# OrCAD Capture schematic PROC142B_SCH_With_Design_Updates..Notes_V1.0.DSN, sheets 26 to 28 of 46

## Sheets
26 25. CPSW RGMII_2 ETHERNET PHY: size C; title: CPSW3G RGMII_2 ETHERNET PHY
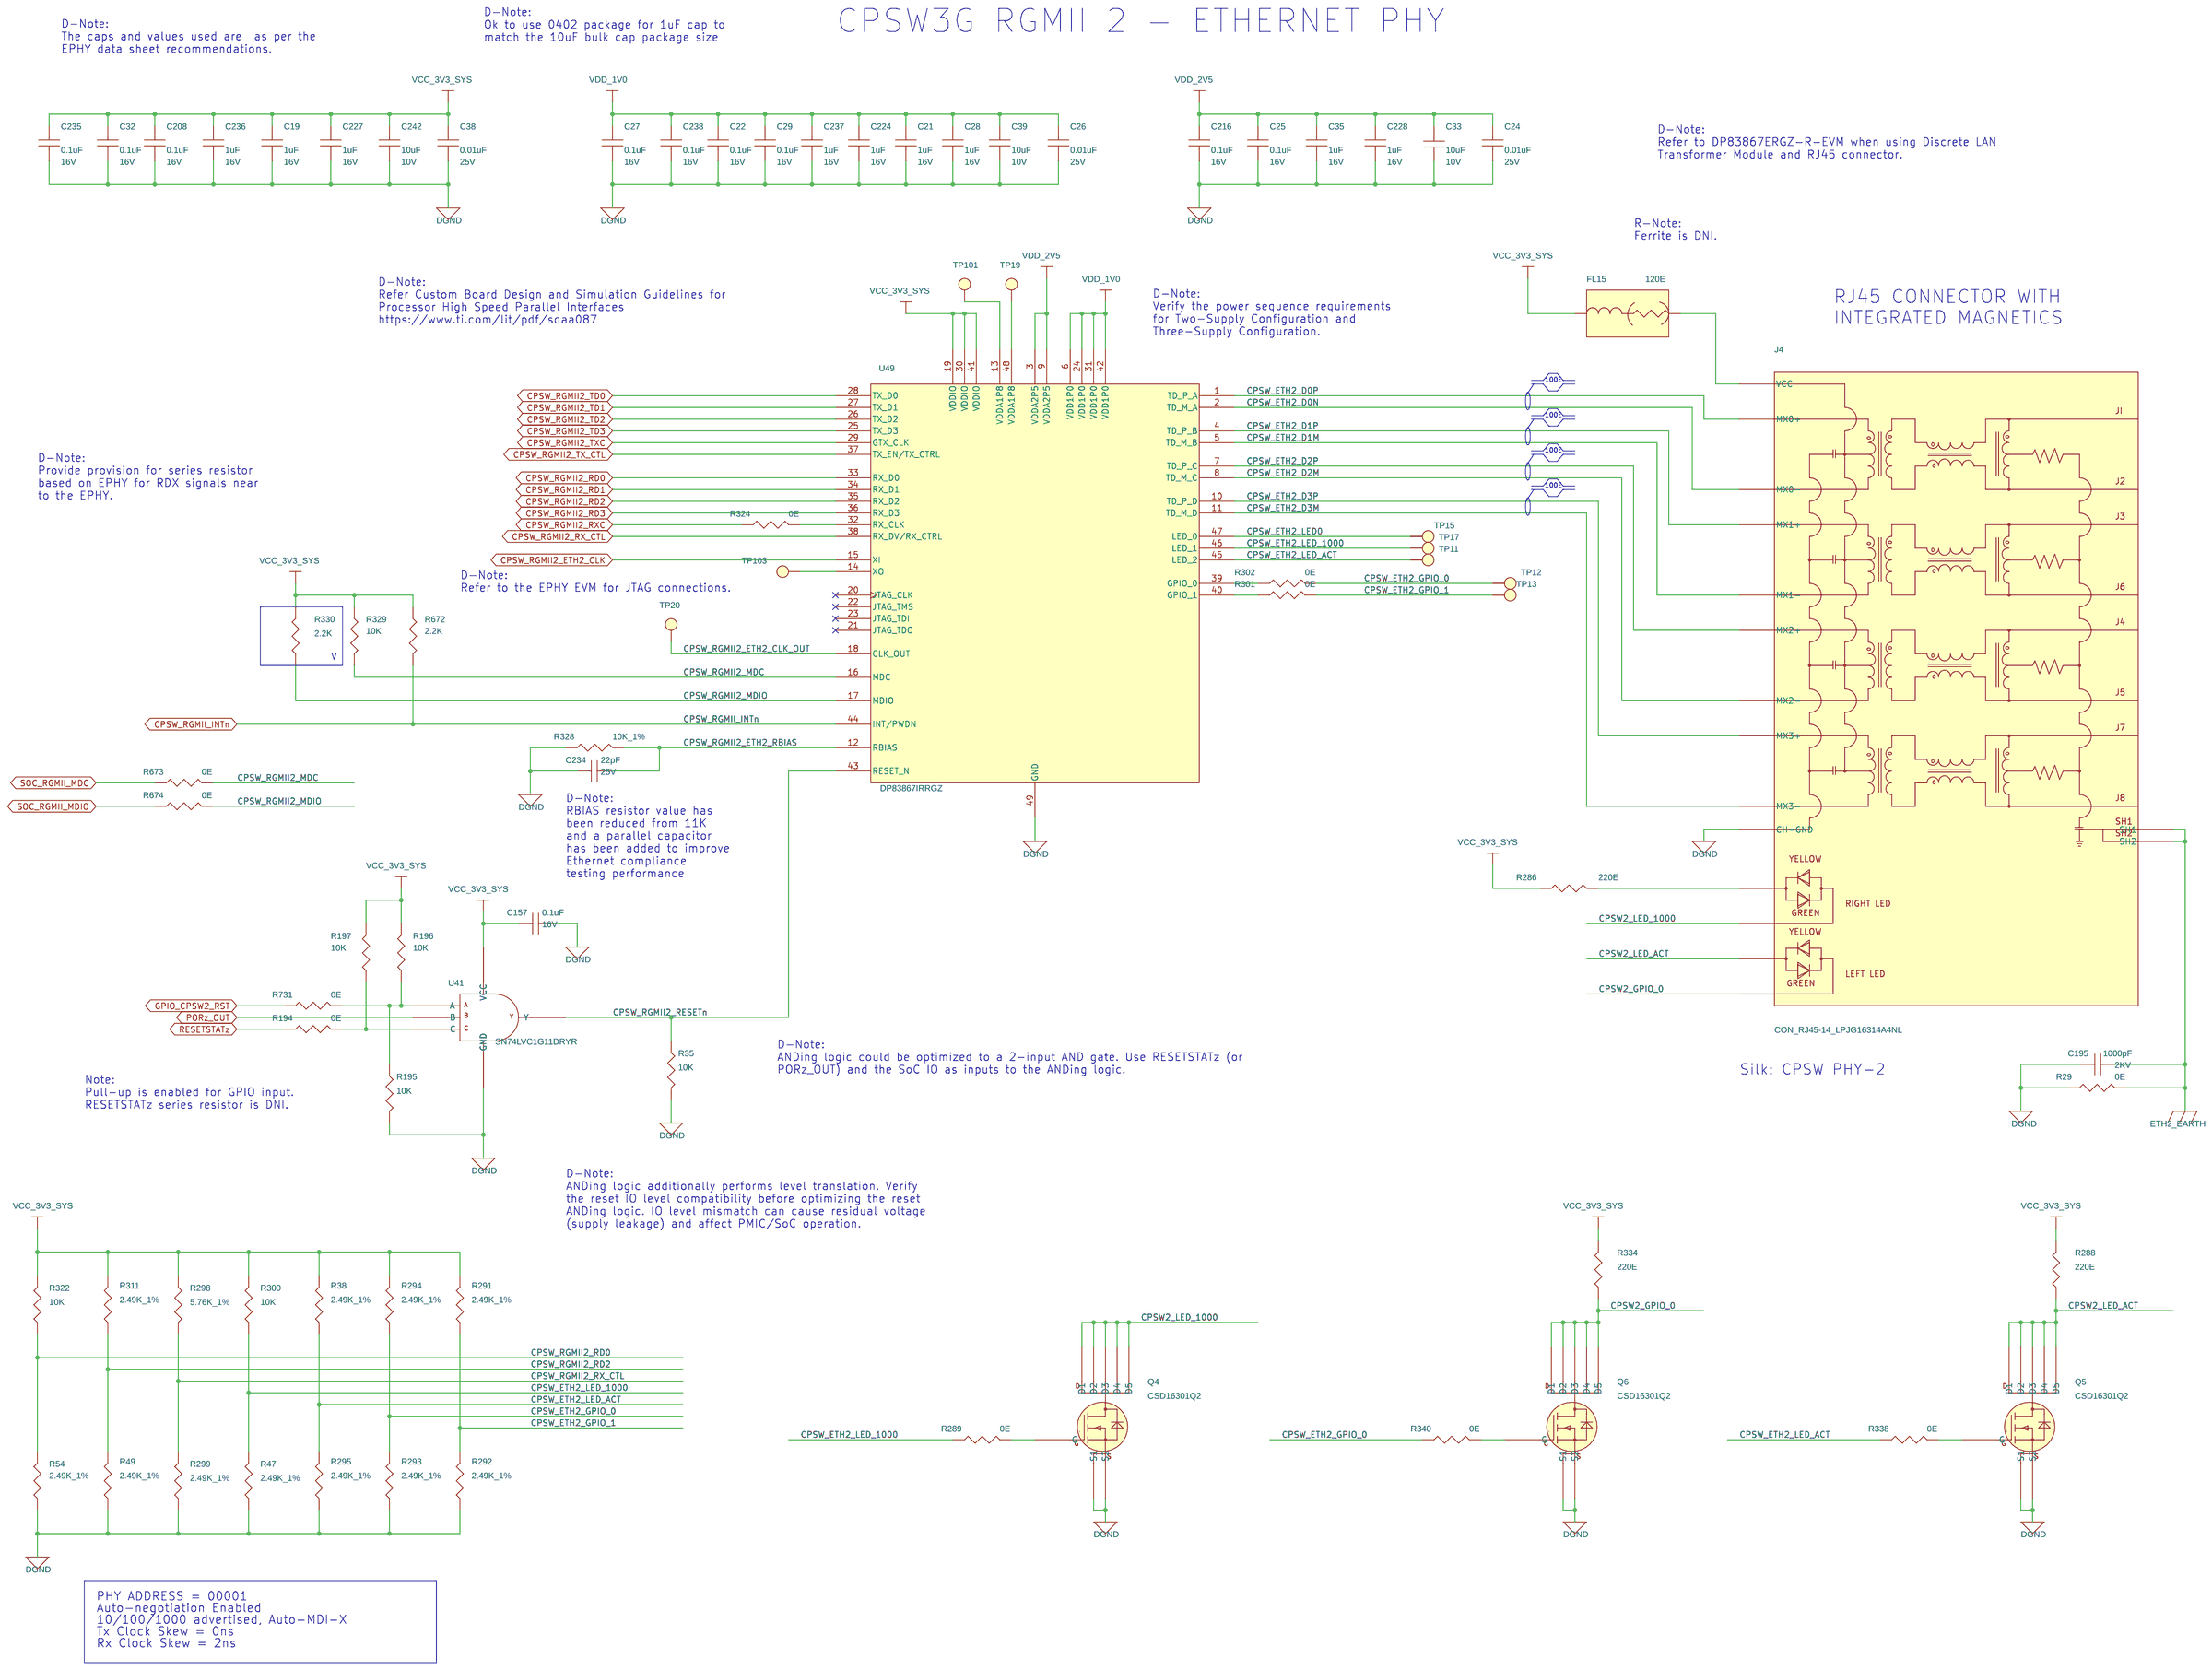
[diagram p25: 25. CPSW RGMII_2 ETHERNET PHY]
27 26. PHY CLK & LED DRIVER: size C; title: SOC MAC INTRFACE, SOC AND ETHERNET PHYs CLOCK BUFFER, LED DRIVER
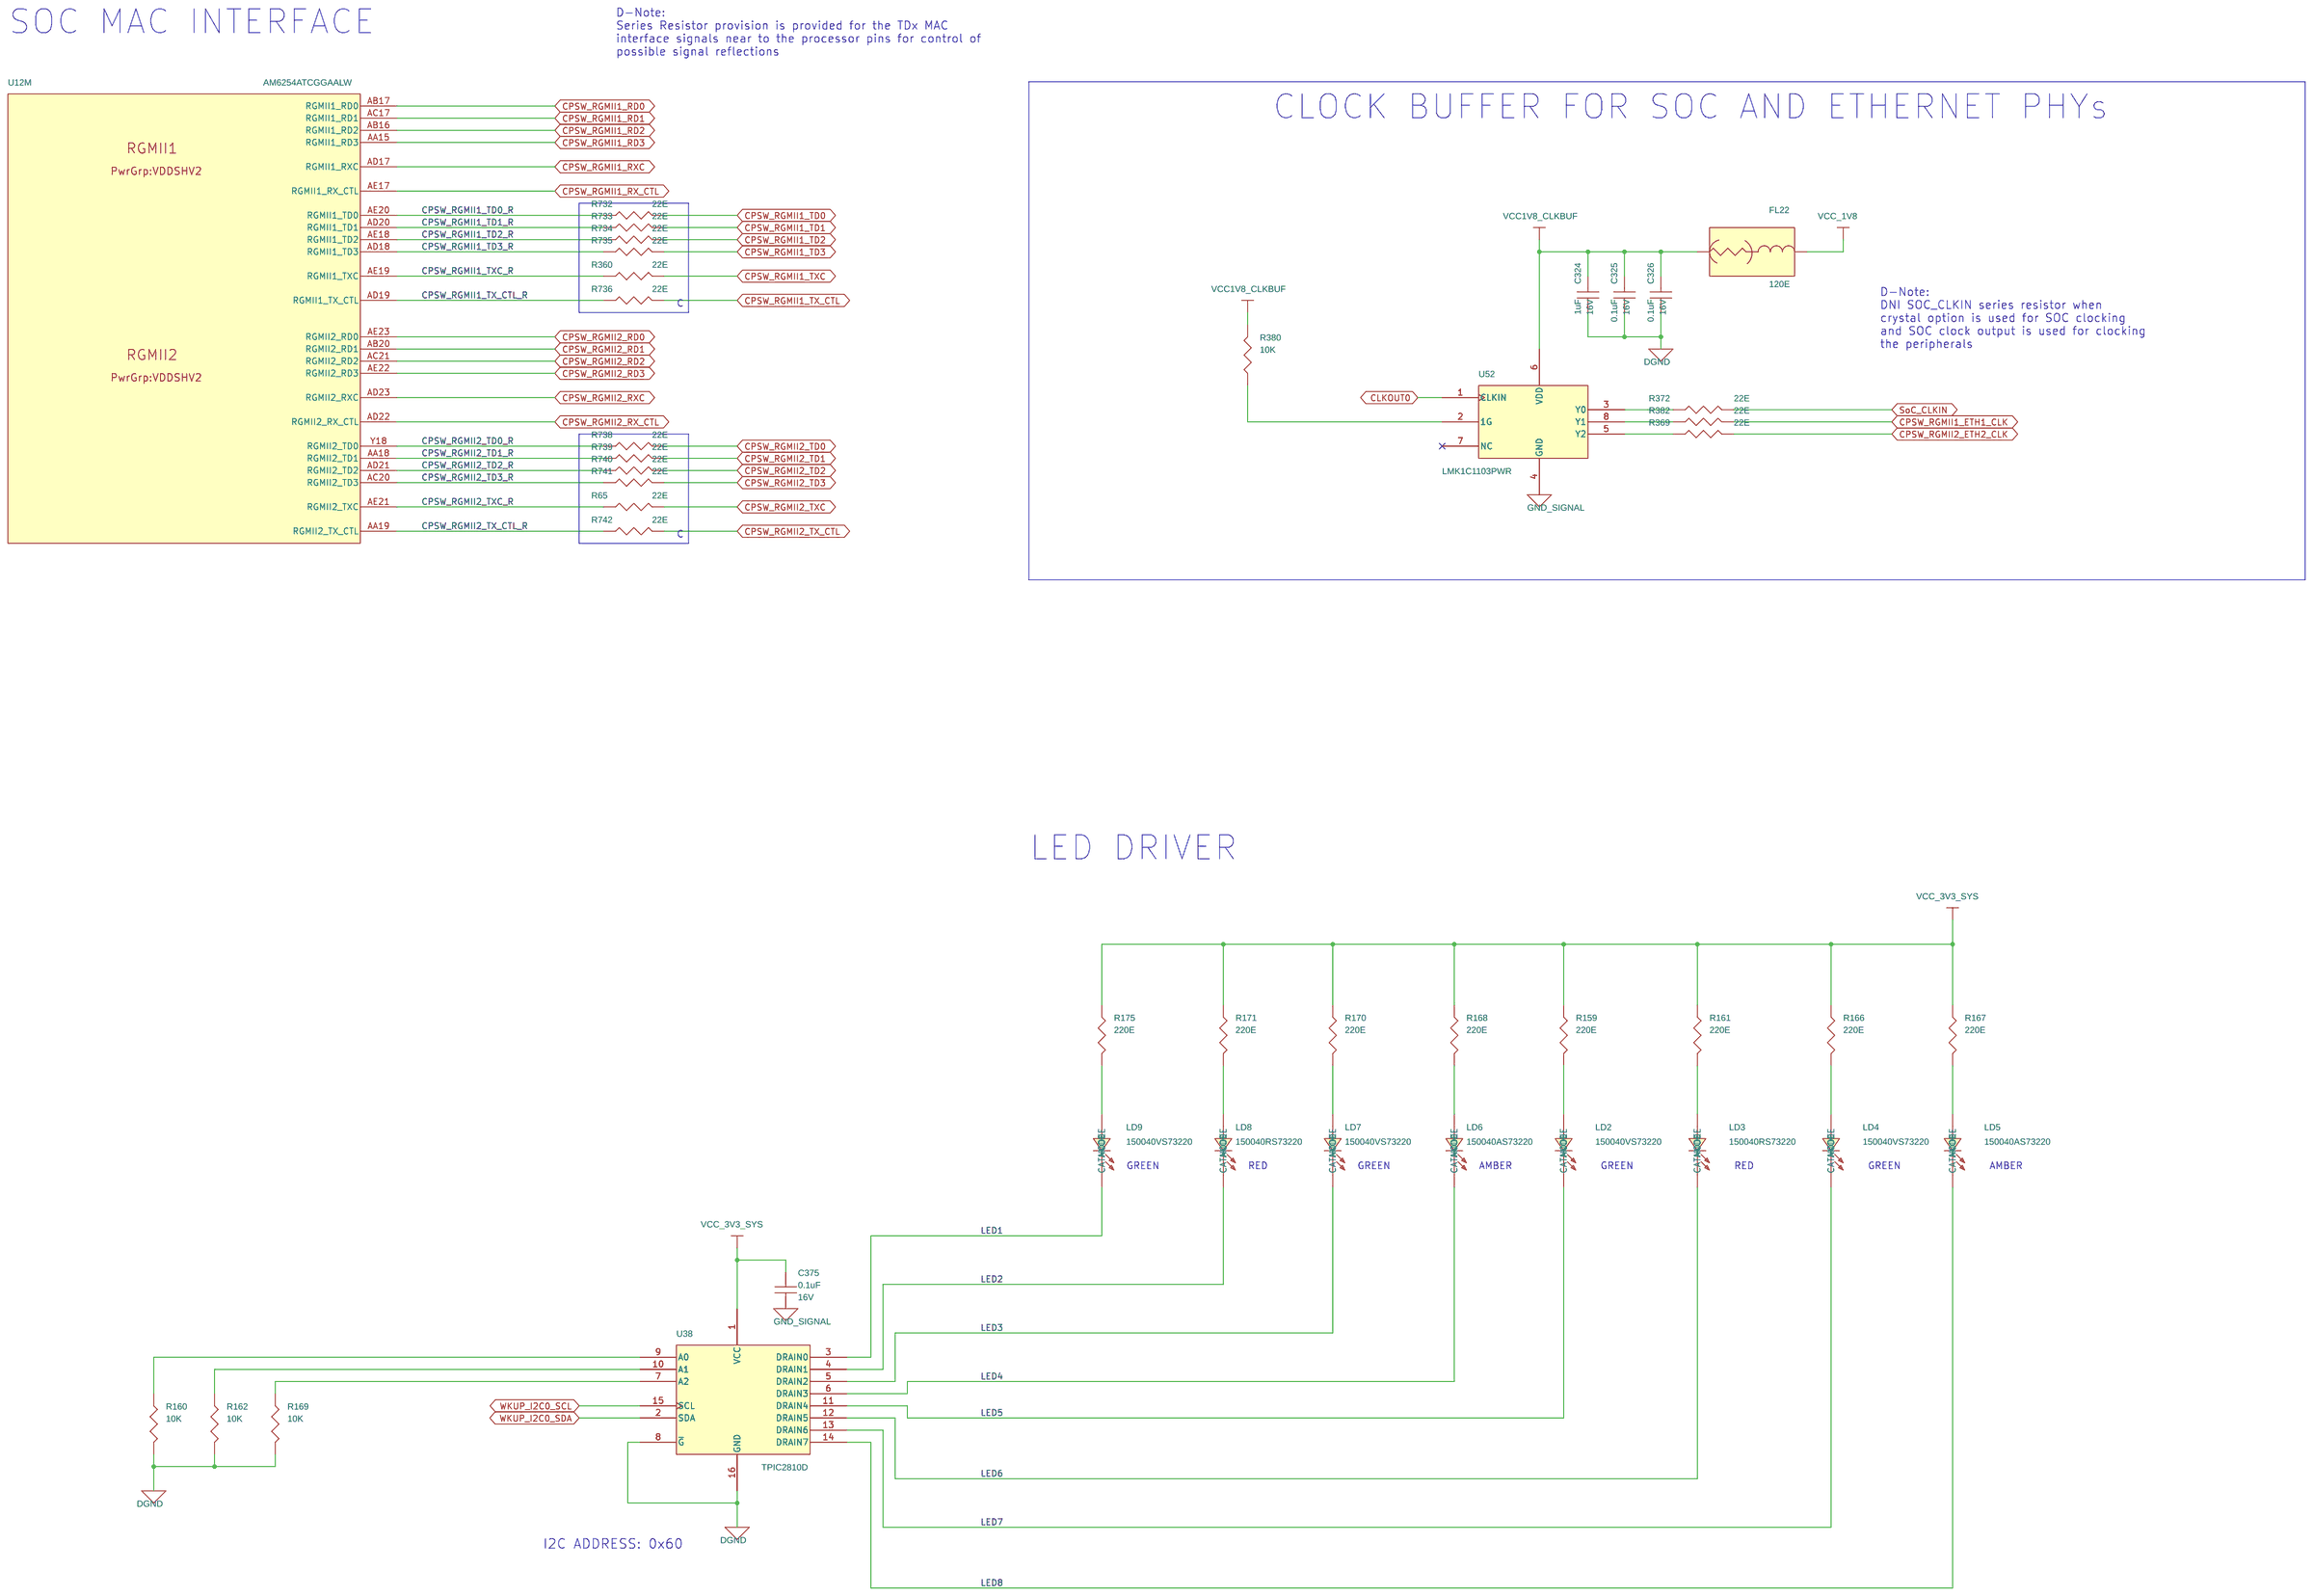
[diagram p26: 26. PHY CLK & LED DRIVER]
28 27. TEST AUTOMATION: size C; title: TEST AUTOMATION
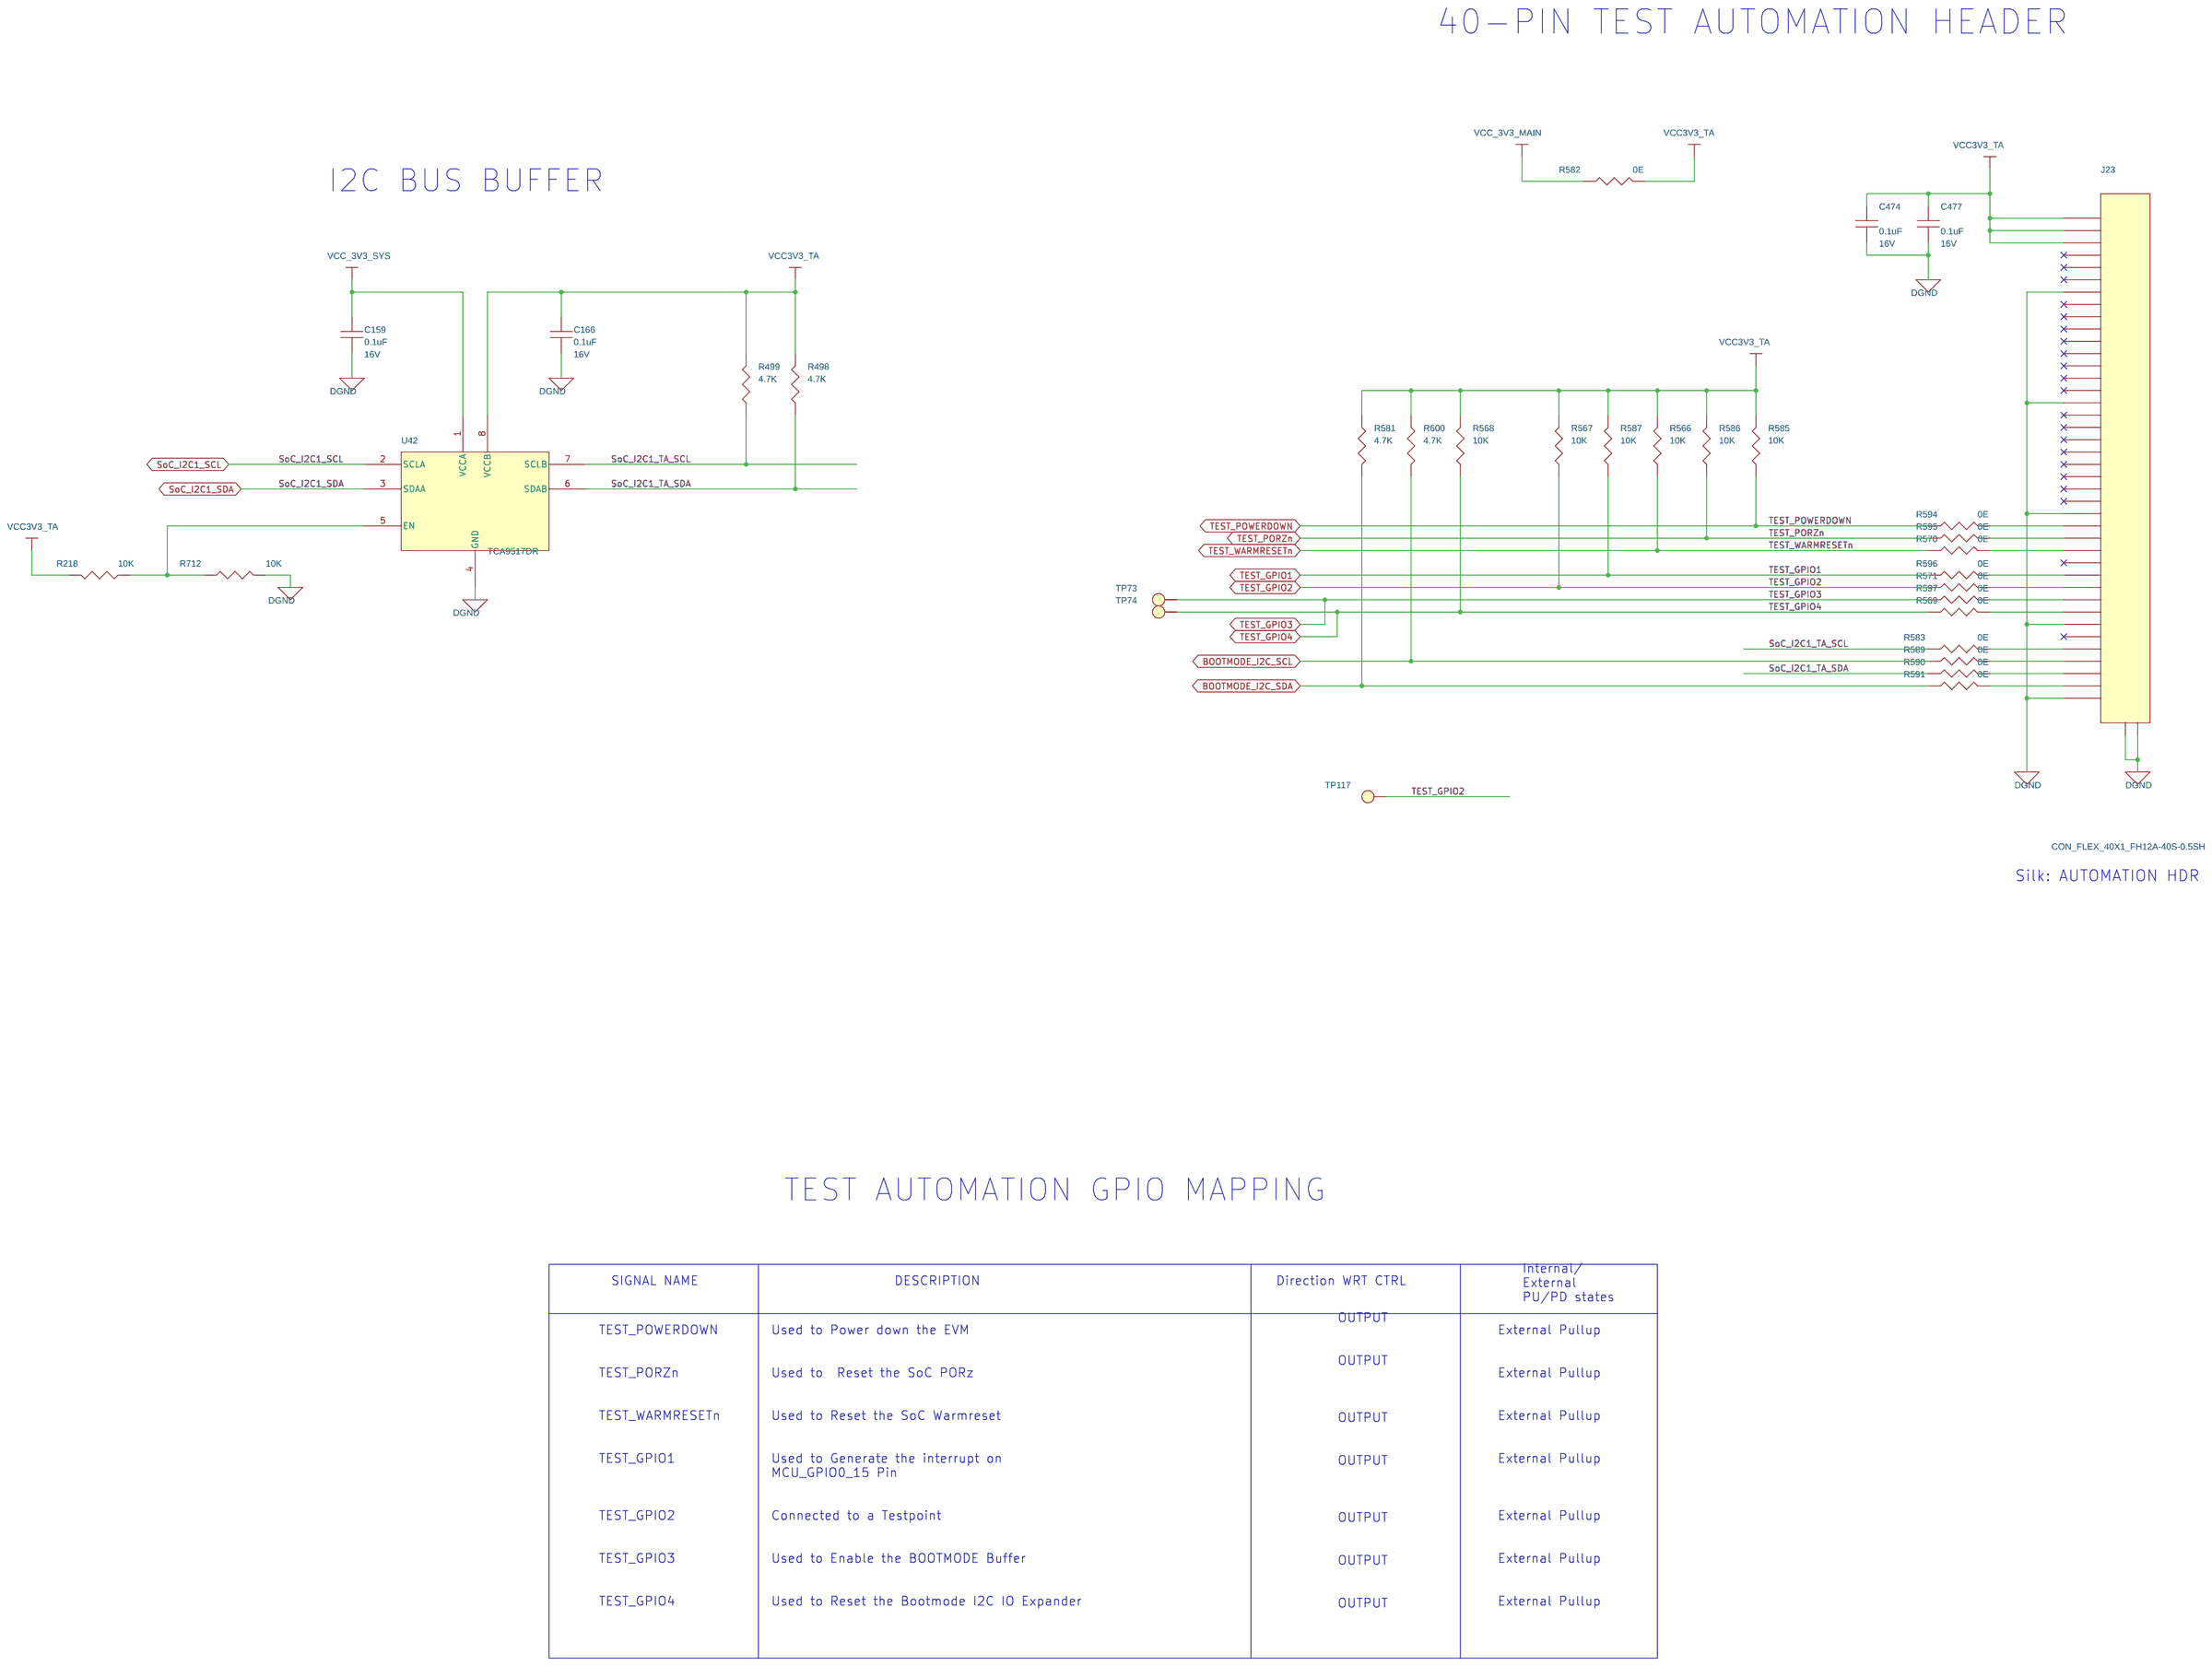
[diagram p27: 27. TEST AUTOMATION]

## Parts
sheet 25. CPSW RGMII_2 ETHERNET PHY
C19  1uF  [CAP0201_0-5]
C21  1uF  [CAP0201_0-5]
C22  0.1uF  [CAP0201_0-5]
C24  0.01uF  [CAP0201_0-5]
C25  0.1uF  [CAP0201_0-5]
C26  0.01uF  [CAP0201_0-5]
C27  0.1uF  [CAP0201_0-5]
C28  1uF  [CAP0201_0-5]
C29  0.1uF  [CAP0201_0-5]
C32  0.1uF  [CAP0201_0-5]
C33  10uF  [CAP0402_0-75]
C35  1uF  [CAP0201_0-5]
C38  0.01uF  [CAP0201_0-5]
C39  10uF  [CAP0402_0-75]
C157  0.1uF  [CAP0201_0-5]
C195  1000pF  [CAP1206_1-75]
C208  0.1uF  [CAP0201_0-5]
C216  0.1uF  [CAP0201_0-5]
C224  1uF  [CAP0201_0-5]
C227  1uF  [CAP0201_0-5]
C228  1uF  [CAP0201_0-5]
C234  22pF  [CAP0201_0-5]
C235  0.1uF  [CAP0201_0-5]
C236  1uF  [CAP0201_0-5]
C237  1uF  [CAP0201_0-5]
C238  0.1uF  [CAP0201_0-5]
C242  10uF  [CAP0402_0-75]
FL15  120E  [EMIFIL_BLM15P_0402]
J4  CON_RJ45-14_LPJG16314A4NL  [CON_RJ45-14_LPJG16314A4NL_S_R_T_13-6]
Q4  CSD16301Q2  [WSON6_CSD13202Q2_80X80_0-8]
Q5  CSD16301Q2  [WSON6_CSD13202Q2_80X80_0-8]
Q6  CSD16301Q2  [WSON6_CSD13202Q2_80X80_0-8]
R29  0E  [RES0603_0-75]
R35  10K  [RES0201_0-5]
R38  2.49K_1%  [RES0402_0-5]
R47  2.49K_1%  [RES0402_0-5]
R49  2.49K_1%  [RES0402_0-5]
R54  2.49K_1%  [RES0402_0-5]
R194  0E  [RES0402_0-5]
R195  10K  [RES0201_0-5]
R196  10K  [RES0201_0-5]
R197  10K  [RES0201_0-5]
R286  220E  [RES0402_0-5]
R288  220E  [RES0402_0-5]
R289  0E  [RES0402_0-5]
R291  2.49K_1%  [RES0402_0-5]
R292  2.49K_1%  [RES0402_0-5]
R293  2.49K_1%  [RES0402_0-5]
R294  2.49K_1%  [RES0402_0-5]
R295  2.49K_1%  [RES0402_0-5]
R298  5.76K_1%  [RES0402_0-5]
R299  2.49K_1%  [RES0402_0-5]
R300  10K  [RES0201_0-5]
R301  0E  [RES0201_0-5]
R302  0E  [RES0201_0-5]
R311  2.49K_1%  [RES0402_0-5]
R322  10K  [RES0201_0-5]
R324  0E  [RES0402_0-5]
R328  10K_1%  [RES0201_0-5]
R329  10K  [RES0201_0-5]
R330  2.2K  [RES0201_0-5]
R334  220E  [RES0402_0-5]
R338  0E  [RES0402_0-5]
R340  0E  [RES0402_0-5]
R672  2.2K  [RES0201_0-5]
R673  0E  [RES0402_0-5]
R674  0E  [RES0402_0-5]
R731  0E  [RES0402_0-5]
TP11  TP20_SMD  [TP20_SMD]
TP12  TP20_SMD  [TP20_SMD]
TP13  TP20_SMD  [TP20_SMD]
TP15  TP20_SMD  [TP20_SMD]
TP17  TP20_SMD  [TP20_SMD]
TP19  TP20_SMD  [TP20_SMD]
TP20  TP20_SMD  [TP20_SMD]
TP101  TP20_SMD  [TP20_SMD]
TP103  TP20_SMD  [TP20_SMD]
U41  SN74LVC1G11DRYR  [SON6_SN74LVC2G17_40X60_0-6]
U49  DP83867IRRGZ  [QFN48_19-68_280X280_1]
sheet 26. PHY CLK & LED DRIVER
C324  1uF  [CAP0201_0-5]
C325  0.1uF  [CAP0201_0-5]
C326  0.1uF  [CAP0201_0-5]
C375  0.1uF  [CAP0201_0-5]
FL22  120E  [EMIFIL_BLM15A_0402_0-6]
LD2  150040VS73220  [LED_150040GS73220_40X20_SMD_0-4]
LD3  150040RS73220  [LED_150040GS73220_40X20_SMD_0-4]
LD4  150040VS73220  [LED_150040GS73220_40X20_SMD_0-4]
LD5  150040AS73220  [LED_150040GS73220_40X20_SMD_0-4]
LD6  150040AS73220  [LED_150040GS73220_40X20_SMD_0-4]
LD7  150040VS73220  [LED_150040GS73220_40X20_SMD_0-4]
LD8  150040RS73220  [LED_150040GS73220_40X20_SMD_0-4]
LD9  150040VS73220  [LED_150040GS73220_40X20_SMD_0-4]
R65  22E  [RES0201_0-5]
R159  220E  [RES0402_0-5]
R160  10K  [RES0201_0-5]
R161  220E  [RES0402_0-5]
R162  10K  [RES0201_0-5]
R166  220E  [RES0402_0-5]
R167  220E  [RES0402_0-5]
R168  220E  [RES0402_0-5]
R169  10K  [RES0201_0-5]
R170  220E  [RES0402_0-5]
R171  220E  [RES0402_0-5]
R175  220E  [RES0402_0-5]
R360  22E  [RES0201_0-5]
R369  22E  [RES0402_0-5]
R372  22E  [RES0402_0-5]
R380  10K  [RES0201_0-5]
R382  22E  [RES0402_0-5]
R732  22E  [RES0201_0-5]
R733  22E  [RES0201_0-5]
R734  22E  [RES0201_0-5]
R735  22E  [RES0201_0-5]
R736  22E  [RES0201_0-5]
R738  22E  [RES0201_0-5]
R739  22E  [RES0201_0-5]
R740  22E  [RES0201_0-5]
R741  22E  [RES0201_0-5]
R742  22E  [RES0201_0-5]
U38  TPIC2810D  [SOIC16_1-8]
U52  LMK1C1103PWR  [TSSOP8_25-59_125X180_1-2]
sheet 27. TEST AUTOMATION
C159  0.1uF  [CAP0201_0-5]
C166  0.1uF  [CAP0201_0-5]
C474  0.1uF  [CAP0201_0-5]
C477  0.1uF  [CAP0201_0-5]
J23  CON_FLEX_40X1_FH12A-40S-0.5SH  [CON_FLEX40X1_FH12A_S_R_S]
R218  10K  [RES0201_0-5]
R498  4.7K  [RES0201_0-5]
R499  4.7K  [RES0201_0-5]
R566  10K  [RES0201_0-5]
R567  10K  [RES0201_0-5]
R568  10K  [RES0201_0-5]
R569  0E  [RES0402_0-5]
R570  0E  [RES0402_0-5]
R571  0E  [RES0402_0-5]
R581  4.7K  [RES0201_0-5]
R582  0E  [RES0805_0-75]
R583  0E  [RES0402_0-5]
R585  10K  [RES0201_0-5]
R586  10K  [RES0201_0-5]
R587  10K  [RES0201_0-5]
R589  0E  [RES0402_0-5]
R590  0E  [RES0402_0-5]
R591  0E  [RES0402_0-5]
R594  0E  [RES0402_0-5]
R595  0E  [RES0402_0-5]
R596  0E  [RES0402_0-5]
R597  0E  [RES0402_0-5]
R600  4.7K  [RES0201_0-5]
R712  10K  [RES0201_0-5]
TP73  TP20_SMD  [TP20_SMD]
TP74  TP20_SMD  [TP20_SMD]
TP117  TP20_SMD  [TP20_SMD]
U42  TCA9517DR  [SOIC8_1-8]
sheet 43. HDMI INTERFACE
U12  AM6254ATCGGAALW  [BGA425_19-68_510X510_0-7]  (sections A,B,C,D,E,F,G,H,I,J,K,L,M,N,O,P,Q,R)

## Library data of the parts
C19 C21 C28 C35 C224 C227 C228 C236 C237 C324 = CAP: CAP CERAMIC 1uF 16V 20% X5R 0201; Chkd/date: MANIRAJA/300520; Crtd /date: ALVY/260520; Custom_Duty: 15%; Customs_HS_Code: 85322990; Distributor_name: DIGIKEY; Distributor_part_number: 490-18654-1-ND; Footprint Path: Y:\MIS_DATABASE\Library\ALTIUM_TOOL\PCB_FOOTPRINTS\Altium_Footprint_Lib.PcbLib; Height: 0.39MM; Library Path: Y:\MIS_DATABASE\Library\ALTIUM_TOOL\SCHEMATICS_PARTS\MS_DISCRETE_Library.schlib; Mfr_name: MURATA; Mfr_part_number: GRM033R61C105ME15D; Mistral Part No: 120018090038-R; Package: 0201; Part_type: CAPACITORS\CERAMIC; Project: QCS610_NANOSOM; RoHS: RoHS; Temperature: -55°C+85°C; Tolerance: 20%; Voltage: 16V; Wattage: NA; Weight: 0.33mg; Datasheet: Y:\MIS_DATABASE\DATASHEETS\CAPACITORS\GRM033R61C105ME15.PDF
C22 C25 C27 C29 C32 C157 C159 C166 C208 C216 C235 C238 C325 C326 C375 C474 C477 = CAP: CAP CERAMIC 0.1uF 16V 10% X5R 0201; Alt_Mfr_name: YAGEO AMERICA; Alt_Mfr_part_number: CC0402KRX5R8BB104; Chkd/date: MANIRAJA/230118; Crtd /date: MANIRAJA/230118; Custom_Duty: 15%; Customs_HS_Code: 85322990; Distributor_name: DIGIKEY; Distributor_part_number: 490-14305-1-ND; Footprint Path: Y:\MIS_DATABASE\Library\ALTIUM_TOOL\PCB_FOOTPRINTS\Altium_Footprint_Lib.PcbLib; Height: 0.33MM; Library Path: Y:\MIS_DATABASE\Library\ALTIUM_TOOL\SCHEMATICS_PARTS\MS_DISCRETE_Library.schlib; Mfr_name: MURATA; Mfr_part_number: GRM033R61C104KE14D; Mistral Part No: 120009030072-R; Package: 0201; Part_type: CAPACITORS\CERAMIC; Project: TI_MAXIE_CPB; RoHS: RoHS; Temperature: -55°C+85°C; Tolerance: 10%; Voltage: 16V; Wattage: NA; Weight: 0.33mg; Datasheet: Y:\MIS_DATABASE\DATASHEETS\CAPACITORS\GRM033R61C104KE14.PDF
C24 C26 C38 = CAP: CAP CERAMIC 0.01uF 25V 10% X5R 0201; Chkd/date: MANIRAJA/230118; Crtd /date: MANIRAJA/230118; Custom_Duty: 15%; Customs_HS_Code: 85322990; Distributor_name: DIGIKEY; Distributor_part_number: GRM033R61E103KA12J-ND; Footprint Path: Y:\MIS_DATABASE\Library\ALTIUM_TOOL\PCB_FOOTPRINTS\Altium_Footprint_Lib.PcbLib; Height: 0.33MM; Library Path: Y:\MIS_DATABASE\Library\ALTIUM_TOOL\SCHEMATICS_PARTS\MS_DISCRETE_Library.schlib; Mfr_name: MURATA; Mfr_part_number: GRM033R61E103KA12J; Mistral Part No: 120018010007-R; Package: 0201; Part_type: CAPACITORS\CERAMIC; Project: TI_MAXIE_CPB; RoHS: RoHS; Temperature: -55°C+85°C; Tolerance: 10%; Voltage: 25V; Wattage: NA; Weight: 0.33mg; Datasheet: Y:\MIS_DATABASE\DATASHEETS\CAPACITORS\GRM033R61E103KA12.PDF
C33 C39 C242 = CAP: CAP CERAMIC 10uF 10V 20% X5R 0402; Chkd/date: MANIRAJA/300520; Crtd /date: ALVY/260520; Custom_Duty: 15%; Customs_HS_Code: 85322990; Distributor_name: DIGIKEY; Distributor_part_number: 490-GRM155R61A106ME11DTR-ND; Footprint Path: Y:\MIS_DATABASE\Library\ALTIUM_TOOL\PCB_FOOTPRINTS\Altium_Footprint_Lib.PcbLib; Height: 0.55MM; Library Path: Y:\MIS_DATABASE\Library\ALTIUM_TOOL\SCHEMATICS_PARTS\MS_DISCRETE_Library.schlib; Mfr_name: MURATA; Mfr_part_number: GRM155R61A106ME11D; Mistral Part No: 120013110019-R; Package: 0402; Part_type: CAPACITORS\CERAMIC; Project: QCS610_NANOSOM; RoHS: RoHS; Temperature: -55°C+85°C; Tolerance: 20%; Voltage: 10V; Wattage: NA; Weight: 3.1mg; Datasheet: Y:\MIS_DATABASE\DATASHEETS\CAPACITORS\MURATA-GXX-SER_NOV17.PDF
C195 = CAP: CAP CERAMIC 1000pF 2KV 10% X7R 1206; Chkd/date: SHREESHAIL/291106; Crtd /date: MAZHAR/281106; Custom_Duty: 15%; Customs_HS_Code: 85322990; Distributor_name: DIGIKEY; Distributor_part_number: 478-2956-1-ND; Footprint Path: Y:\MIS_DATABASE\Library\ALTIUM_TOOL\PCB_FOOTPRINTS\Altium_Footprint_Lib.PcbLib; Height: 1.52MM; Library Path: Y:\MIS_DATABASE\Library\ALTIUM_TOOL\SCHEMATICS_PARTS\MS_DISCRETE_Library.schlib; Mfr_name: AVX CORPORATION; Mfr_part_number: 1206GC102KAT1A; Mistral Part No: 120015080006-R; Package: 1206; Part_type: CAPACITORS\CERAMIC; Project: ADR1B; RoHS: RoHS; Temperature: -55°C+125°C; Tolerance: 10%; Voltage: 2KV; Wattage: NA; Weight: 16.2mg; Datasheet: Y:\MIS_DATABASE\DATASHEETS\CAPACITORS\AVX_HV-MLC.PDF
C234 = CAP: CAP CERAMIC 22pF 25V 1% C0G(NP0) 0201; Chkd/date: MANIRAJA/270721; Crtd /date: ALVY/260721; Custom_Duty: 15%; Customs_HS_Code: 85322990; Distributor_name: DIGIKEY; Distributor_part_number: 490-14545-1-ND; Footprint Path: Y:\MIS_DATABASE\Library\ALTIUM_TOOL\PCB_FOOTPRINTS\Altium_Footprint_Lib.PcbLib; Height: 0.33MM; Library Path: Y:\MIS_DATABASE\Library\ALTIUM_TOOL\SCHEMATICS_PARTS\MS_DISCRETE_Library.schlib; Mfr_name: MURATA; Mfr_part_number: GRM0335C1E220FA01D; Mistral Part No: 120021070019-R; Package: 0201; Part_type: CAPACITORS\CERAMIC; Project: TI_AM335x SK_BRD; RoHS: RoHS; Temperature: -55°C+125°C; Tolerance: 1%; Voltage: 25V; Wattage: NA; Weight: 0.33mg; Datasheet: Y:\MIS_DATABASE\DATASHEETS\CAPACITORS\GRM0335C1E220FA01.PDF
FL15 = EMIFILTER_IND: FERRITE CHIP 120E 2A 0402; Chkd/date: NAVEED/241114; Crtd /date: USMAN/170613; Custom_Duty: 24%; Customs_HS_Code: 85369090; Distributor_name: MOUSER; Distributor_part_number: 81-BLM15PX121SN1D; Height: 0.55MM; Mfr_name: MURATA; Mfr_part_number: BLM15PX121SN1D; Mistral Part No: 130013060022-R; Package: 0402; Part_type: FILTER; Project: GEN_3-8; RoHS: RoHS; Temperature: -55°C+125°C; Tolerance: 25%; Voltage: NA; Wattage: NA; Weight: NA; Datasheet: Y:\MIS_DATABASE\DATASHEETS\DISCRETES\INDUCTORS\BLM15X.PDF
J4 = CON_RJ45-14_LPJG16314A4NL: CON RJ-45 FEMALE 14POS RT TH; Chkd/date: VASANTHA/150714; Crtd /date: BALACHANDAR/120614; Custom_Duty: 24%; Customs_HS_Code: 85369090; Distributor_name: NA; Distributor_part_number: NA; Footprint Path: Y:\MIS_DATABASE\Library\ALTIUM_TOOL\PCB_FOOTPRINTS\Altium_Footprint_Lib.PcbLib; Height: 13.60MM; Library Path: Y:\MIS_DATABASE\Library\ALTIUM_TOOL\SCHEMATICS_PARTS\MS_CONNECTOR_Library.schlib; Mfr_name: LINK-PP; Mfr_part_number: LPJG16314A4NL; Mistral Part No: 150014060029-R; Package: THRU-HOLE; Part_type: CONNECTOR\JACK; Project: AEGIS; RoHS: RoHS; Temperature: -0°C+70°C; Tolerance: NA; Voltage: NA; Wattage: NA; Weight: NA; Datasheet: Y:\MIS_DATABASE\DATASHEETS\CONNECTORS\LPJG16314A4NL.PDF
Q4-Q6 = MOSFET_CSD17313Q2: IC MOSFET N-CHANNEL NEXFET 25V WSON6; Chkd/date: ALVY/071220; Crtd /date: MANIRAJA/071220; Custom_Duty: 15%; Customs_HS_Code: 85423100; Distributor_name: DIGIKEY; Distributor_part_number: 296-25260-1-ND; Footprint Path: Y:\MIS_DATABASE\Library\ALTIUM_TOOL\PCB_FOOTPRINTS\Altium_Footprint_Lib.PcbLib; Height: 0.80MM; Library Path: Y:\MIS_DATABASE\Library\ALTIUM_TOOL\SCHEMATICS_PARTS\MS_MOSFET_Library.schlib; Mfr_name: TEXAS INSTRUMENTS; Mistral Part No: 142020120008-R; Package: WSON6; Part_type: ICS\POWER\MOSFET; Project: TI_AM243x LP EVM; RoHS: RoHS; Temperature: -55°C+150°C; Tolerance: NA; Voltage: NA; Wattage: NA; Weight: 8.7mg; Datasheet: Y:\MIS_DATABASE\DATASHEETS\ICS\POWER\CSD16301Q2.PDF
R29 = RESISTOR: RES 0E 1/10W 5% 0603; Chkd/date: MANIRAJA/051217; Crtd /date: BAVISH/180211; Custom_Duty: 15%; Customs_HS_Code: 85332119; Distributor_name: DIGIKEY; Distributor_part_number: 311-0.0GRCT-ND; Footprint Path: Y:\MIS_DATABASE\Library\ALTIUM_TOOL\PCB_FOOTPRINTS\Altium_Footprint_Lib.PcbLib; Height: 0.55MM; Library Path: Y:\MIS_DATABASE\Library\ALTIUM_TOOL\SCHEMATICS_PARTS\MS_DISCRETE_Library.schlib; Manufacturer: YAGEO AMERICA; Mfr_name: PANASONIC-ECG; Mfr_part_number: RC0603JR-070RL; Mistral Part No: 110011020013-R; Package: 0603; Part_type: RESISTORS\FIXED; Project: KENNEL; RoHS: RoHS; Temperature: -55°C+155°C; Tolerance: 5%; Voltage: NA; Wattage: 1/10W; Weight: 2mg; Datasheet: Y:\MIS_DATABASE\DATASHEETS\RESISTORS\RCXXXXL-SER_MAR18.PDF
R35 R160 R162 R169 R195-R197 R218 R300 R322 R329 R380 R566-R568 R585-R587 R712 = RESISTOR: RES 10K 1/20W 5% 0201; Chkd/date: MANIRAJA/050517; Crtd /date: MANIRAJA/050517; Custom_Duty: 15%; Customs_HS_Code: 85332119; Distributor_name: DIGIKEY; Distributor_part_number: 311-10KNCT-ND; Footprint Path: Y:\MIS_DATABASE\Library\ALTIUM_TOOL\PCB_FOOTPRINTS\Altium_Footprint_Lib.PcbLib; Height: 0.26MM; Library Path: Y:\MIS_DATABASE\Library\ALTIUM_TOOL\SCHEMATICS_PARTS\MS_DISCRETE_Library.schlib; Mfr_name: YAGEO AMERICA; Mfr_part_number: RC0201JR-0710KL; Mistral Part No: 110010070051-R; Package: 0201; Part_type: RESISTORS\FIXED; Project: GOLDEN-I LITE; RoHS: RoHS; Temperature: -55°C+125°C; Tolerance: 5%; Voltage: NA; Wattage: 1/20W; Weight: 0.17mg; Datasheet: Y:\MIS_DATABASE\DATASHEETS\RESISTORS\RCXXXXL-SER_MAR18.PDF
R38 R47 R49 R54 R291-R295 R299 R311 = RESISTOR: RES 2.49K 1/16W 1% 0402; Chkd/date: VASANTHA/270516; Crtd /date: VASANTHA/270516; Custom_Duty: 15%; Customs_HS_Code: 85332119; Distributor_name: DIGIKEY; Distributor_part_number: 311-2.49KLRCT-ND; Footprint Path: Y:\MIS_DATABASE\Library\ALTIUM_TOOL\PCB_FOOTPRINTS\Altium_Footprint_Lib.PcbLib; Height: 0.40MM; Library Path: Y:\MIS_DATABASE\Library\ALTIUM_TOOL\SCHEMATICS_PARTS\MS_DISCRETE_Library.schlib; Mfr_name: YAGEO AMERICA; Mfr_part_number: RC0402FR-072K49L; Mistral Part No: 110016050020-R; Package: 0402; Part_type: RESISTORS\FIXED; Project: TMDXCSKCC; RoHS: RoHS; Temperature: -55°C+155°C; Tolerance: 1%; Voltage: NA; Wattage: 1/16W; Weight: 0.65mg; Datasheet: Y:\MIS_DATABASE\DATASHEETS\RESISTORS\RCXXXXL-SER_MAR18.PDF
R194 R289 R338 R340 R569-R571 R583 R589-R591 R594-R597 R673 R674 R731 = RESISTOR: RES 0E 1/16W JUMPER 0402; Chkd/date: VASANTHA/201216; Crtd /date: MUDDU/190810; Custom_Duty: 15%; Customs_HS_Code: 85332119; Distributor_name: DIGIKEY; Distributor_part_number: 541-0.0JCT-ND; Footprint Path: Y:\MIS_DATABASE\Library\ALTIUM_TOOL\PCB_FOOTPRINTS\Altium_Footprint_Lib.PcbLib; Height: 0.40MM; Library Path: Y:\MIS_DATABASE\Library\ALTIUM_TOOL\SCHEMATICS_PARTS\MS_DISCRETE_Library.schlib; Mfr_name: VISHAY; Mfr_part_number: CRCW04020000Z0ED; Mistral Part No: 110010080019-R; Package: 0402; Part_type: RESISTORS\FIXED; Project: PB_BUGBASE; RoHS: RoHS; Temperature: -55°C+155°C; Tolerance: NA; Voltage: NA; Wattage: 1/16W; Weight: 0.65mg; Datasheet: Y:\MIS_DATABASE\DATASHEETS\RESISTORS\CRCW0603.PDF
R286 R288 R334 = RESISTOR: RES 220E 1/10W 5% 0402; Chkd/date: VASANTHA/291216; Crtd /date: GEETHA/260406; Custom_Duty: 15%; Customs_HS_Code: 85332119; Distributor_name: DIGIKEY; Distributor_part_number: P220JCT-ND; Footprint Path: Y:\MIS_DATABASE\Library\ALTIUM_TOOL\PCB_FOOTPRINTS\Altium_Footprint_Lib.PcbLib; Height: 0.40MM; Library Path: Y:\MIS_DATABASE\Library\ALTIUM_TOOL\SCHEMATICS_PARTS\MS_DISCRETE_Library.schlib; Mfr_name: PANASONIC-ECG; Mfr_part_number: ERJ-2GEJ221X; Mistral Part No: 110009030506-R; Package: 0402; Part_type: RESISTORS\FIXED; Project: RED EYE; RoHS: RoHS; Temperature: -55°C+155°C; Tolerance: 5%; Voltage: NA; Wattage: 1/10W; Weight: 0.8mg; Datasheet: Y:\MIS_DATABASE\DATASHEETS\RESISTORS\PAN-ERJSER_NOV17.PDF
R298 = RESISTOR: RES 5.76K 1/10W 1% 0402; Chkd/date: MAZHAR/150709; Crtd /date: USMAN/220808; Custom_Duty: 15%; Customs_HS_Code: 85332119; Distributor_name: DIGIKEY; Distributor_part_number: P5.76KLCT-ND; Footprint Path: Y:\MIS_DATABASE\Library\ALTIUM_TOOL\PCB_FOOTPRINTS\Altium_Footprint_Lib.PcbLib; Height: 0.40MM; Library Path: Y:\MIS_DATABASE\Library\ALTIUM_TOOL\SCHEMATICS_PARTS\MS_DISCRETE_Library.schlib; Mfr_name: PANASONIC-ECG; Mfr_part_number: ERJ-2RKF5761X; Mistral Part No: 110009030945-R; Package: 0402; Part_type: RESISTORS\FIXED; Project: CPB; RoHS: RoHS; Temperature: -55°C+155°C; Tolerance: 1%; Voltage: NA; Wattage: 1/10W; Weight: 0.8mg; Datasheet: Y:\MIS_DATABASE\DATASHEETS\RESISTORS\PAN-ERJSER_NOV17.PDF
R301 R302 = RESISTOR: RES 0E 1/20W 5% 0201; Chkd/date: NAVEED/301214; Crtd /date: MUDDU/120710; Custom_Duty: 15%; Customs_HS_Code: 85332119; Distributor_name: DIGIKEY; Distributor_part_number: 311-0.0NCT-ND; Footprint Path: Y:\MIS_DATABASE\Library\ALTIUM_TOOL\PCB_FOOTPRINTS\Altium_Footprint_Lib.PcbLib; Height: 0.26MM; Library Path: Y:\MIS_DATABASE\Library\ALTIUM_TOOL\SCHEMATICS_PARTS\MS_DISCRETE_Library.schlib; Mfr_name: YAGEO AMERICA; Mfr_part_number: RC0201JR-070RL; Mistral Part No: 110010070067-R; Package: 0201; Part_type: RESISTORS\FIXED; Project: PB_BUGBASE; RoHS: RoHS; Temperature: -55°C+125°C; Tolerance: 5%; Voltage: NA; Wattage: 1/20W; Weight: 0.17mg; Datasheet: Y:\MIS_DATABASE\DATASHEETS\RESISTORS\RCXXXXL-SER_MAR18.PDF
R324 = RESISTOR: RES 0E 1/16W JUMPER 0402; Chkd/date: VASANTHA/201216; Crtd /date: MUDDU/190810; Custom_Duty: 15%; Customs_HS_Code: 85332119; Distributor_name: DIGIKEY; Distributor_part_number: 541-0.0JCT-ND; Footprint Path: Y:\MIS_DATABASE\Library\ALTIUM_TOOL\PCB_FOOTPRINTS\Altium_Footprint_Lib.PcbLib; Height: 0.40MM; Library Path: Y:\MIS_DATABASE\Library\ALTIUM_TOOL\SCHEMATICS_PARTS\MS_DISCRETE_Library.schlib; Mfr_name: VISHAY; Mfr_part_number: CRCW04020000Z0ED; Mistral Part No: 110010080019-R; Package: 0402; Part_type: RESISTORS\FIXED; Project: PB_BUGBASE; RoHS: RoHS; SIGNAL_MODEL: RESISTOR_RES0402_0-5_0E_0E; Temperature: -55°C+155°C; Tolerance: NA; Voltage: NA; Wattage: 1/16W; Weight: 0.65mg; Datasheet: Y:\MIS_DATABASE\DATASHEETS\RESISTORS\CRCW0603.PDF
R328 = RESISTOR: RES 10K 1/20W 1% 0201; Chkd/date: VASANTHA/270117; Crtd /date: MANIRAJA/270117; Custom_Duty: 15%; Customs_HS_Code: 85332119; Distributor_name: DIGIKEY; Distributor_part_number: 311-10.0KMCT-ND; Footprint Path: Y:\MIS_DATABASE\Library\ALTIUM_TOOL\PCB_FOOTPRINTS\Altium_Footprint_Lib.PcbLib; Height: 0.26MM; Library Path: Y:\MIS_DATABASE\Library\ALTIUM_TOOL\SCHEMATICS_PARTS\MS_DISCRETE_Library.schlib; Manufacturer: YAGEO AMERICA; Mfr_name: YAGEO AMERICA; Mfr_part_number: RC0201FR-0710KL; Mistral Part No: 110011040018-R; Package: 0201; Part_type: RESISTORS\FIXED; Project: GOLDEN-I LITE; RoHS: RoHS; Temperature: -55°C+125°C; Tolerance: 1%; Voltage: NA; Wattage: 1/20W; Weight: 0.17mg; Datasheet: Y:\MIS_DATABASE\DATASHEETS\RESISTORS\RCXXXXL-SER_MAR18.PDF
R330 R672 = RESISTOR: RES 2.2K 1/20W 5% 0201; Chkd/date: VASANTHA/010117; Crtd /date: MAZHAR/010605; Custom_Duty: 15%; Customs_HS_Code: 85332119; Distributor_name: DIGIKEY; Distributor_part_number: P2.2KAGCT-ND; Footprint Path: Y:\MIS_DATABASE\Library\ALTIUM_TOOL\PCB_FOOTPRINTS\Altium_Footprint_Lib.PcbLib; Height: 0.26MM; Library Path: Y:\MIS_DATABASE\Library\ALTIUM_TOOL\SCHEMATICS_PARTS\MS_DISCRETE_Library.schlib; Mfr_name: PANASONIC-ECG; Mfr_part_number: ERJ-1GEJ222C; Mistral Part No: 110009030427-R; Package: 0201; Part_type: RESISTORS\FIXED; Project: G4SLIM; RoHS: RoHS; Temperature: -55°C+125°C; Tolerance: 5%; Voltage: NA; Wattage: 1/20W; Weight: 0.15mg; Datasheet: Y:\MIS_DATABASE\DATASHEETS\RESISTORS\PAN-ERJXGE-FEB06.PDF
TP11-TP13 TP15 TP17 TP19 TP20 TP73 TP74 TP101 TP103 TP117 = TESTPOINT: TESTPOINT CIR 20 SMD; Chkd/date: SHREESHAIL/171006; Crtd /date: MAZHAR/171006; Custom_Duty: NA; Customs_HS_Code: NA; Distributor_name: NA; Distributor_part_number: NA; Footprint Path: Y:\MIS_DATABASE\Library\ALTIUM_TOOL\PCB_FOOTPRINTS\Altium_Footprint_Lib.PcbLib; Height: NA; Library Path: Y:\MIS_DATABASE\Library\ALTIUM_TOOL\SCHEMATICS_PARTS\MS_DISCRETE_Library.schlib; MECHANICAL 3D STEP FILE: NA; Mfr_name: LOCAL; Mistral Part No: NA; Package: SMD; Project: BT MODULE_CSRBC04; RoHS: NA; Temperature: NA; Tolerance: NA; Voltage: NA; Wattage: NA; Weight: NA; Datasheet: NA
U41 = SN74LVC1G11DCKR_SC70-6: IC SINGLE 3-INPUT POSITIVE-AND GATE SON6; Chkd/date: MANIRAJA/270121; Crtd /date: ALVY/270121; Custom_Duty: 15%; Customs_HS_Code: 85423100; Distributor_name: DIGIKEY; Distributor_part_number: 296-30120-1-ND; Footprint Path: Y:\MIS_DATABASE\Library\ALTIUM_TOOL\PCB_FOOTPRINTS\Altium_Footprint_Lib.PcbLib; Height: 0.60MM; Library Path: Y:\MIS_DATABASE\Library\ALTIUM_TOOL\SCHEMATICS_PARTS\MS_GATE_Library.schlib; Mfr_name: TEXAS INSTRUMENTS; Mistral Part No: 141021010013-R; Package: SON6; Part_type: ICS\DIGITAL\GATES; Project: AM64X_SKEVM; RoHS: RoHS; Temperature: -40°C+125°C; Tolerance: NA; Voltage: NA; Wattage: NA; Weight: 33mg; Datasheet: Y:\MIS_DATABASE\DATASHEETS\ICS\DIGITAL\GATES\SN74LVC1G_NOV16.PDF
U49 = DP83867IRRGZ_VQFN48: IC HIGH IMMUNITY 10/100/1000 Mb/s ETHERNET PHY LAYER TRANSCEIVER VQFN48; Chkd/date: MANIRAJA/110817; Crtd /date: MANIRAJA/110817; Custom_Duty: 15%; Customs_HS_Code: 85423100; Distributor_name: DIGIKEY; Distributor_part_number: DP83867IRRGZT-ND; Height: 1.00MM; Mfr_name: TEXAS INSTRUMENTS; Mistral Part No: 143017080002-R; Package: VQFN48; Part_type: ICS\TELECOM\TRANSCEIVER; Project: TI_SVB_CONTROLLER CARD; RoHS: RoHS; Temperature: -40°C+85°C; Tolerance: NA; Voltage: NA; Wattage: NA; Weight: NA; Datasheet: Y:\MIS_DATABASE\DATASHEETS\ICS\DIGITAL\BUSTRANSCEIVER\DP83867I.PDF
FL22 = EMIFILTER_IND: IND FERRITE BEAD CHIP 120E 2A 0402; Chkd/date: NAVEED/241114; Crtd /date: USMAN/170613; Custom_Duty: 24%; Customs_HS_Code: 85369090; Distributor_name: DIGIKEY; Distributor_part_number: 490-9656-1-ND; Footprint Path: Y:\MIS_DATABASE\Library\ALTIUM_TOOL\PCB_FOOTPRINTS\Altium_Footprint_Lib.PcbLib; Height: 0.55MM; Library Path: Y:\MIS_DATABASE\Library\ALTIUM_TOOL\SCHEMATICS_PARTS\MS_FILTER_Library.schlib; Mfr_name: MURATA; Mfr_part_number: BLM15PX121SN1D; Mistral Part No: 130013060022-R; Package: 0402; Part_type: INDUCTOR; Project: GEN_3-8; RoHS: RoHS; Temperature: -55°C+125°C; Tolerance: 25%; Voltage: NA; Wattage: NA; Weight: 1mg; Datasheet: Y:\MIS_DATABASE\DATASHEETS\DISCRETES\INDUCTORS\BLM15-SN1-SER.PDF
LD2 LD4 LD7 LD9 = DIODE_LED: DIODE LED BRIGHT GREEN SMD; Chkd/date: MANIRAJA/261120; Crtd /date: ALVY/261120; Custom_Duty: 24%; Customs_HS_Code: 85439000; Distributor_name: DIGIKEY; Distributor_part_number: 732-13425-1-ND; Footprint Path: Y:\MIS_DATABASE\Library\ALTIUM_TOOL\PCB_FOOTPRINTS\Altium_Footprint_Lib.PcbLib; Height: 0.35MM; Library Path: Y:\MIS_DATABASE\Library\ALTIUM_TOOL\SCHEMATICS_PARTS\MS_OPTO_Library.schlib; Mfr_name: WURTH ELECTRONIK; Mistral Part No: 130020110071-R; Package: SMD; Part_type: OPTO\LED; Project: AM64X_SKEVM; RoHS: RoHS; Temperature: -40°C+85°C; Tolerance: NA; Voltage: NA; Wattage: NA; Weight: 29.3mg; Datasheet: Y:\MIS_DATABASE\DATASHEETS\DISCRETES\LEDS\150040VS73220.PDF
LD3 LD8 = DIODE_LED: DIODE LED RED SMD; Chkd/date: MANIRAJA/100920; Crtd /date: ALVY/100920; Custom_Duty: 24%; Customs_HS_Code: 85439000; Distributor_name: DIGIKEY; Distributor_part_number: 732-13422-1-ND; Footprint Path: Y:\MIS_DATABASE\Library\ALTIUM_TOOL\PCB_FOOTPRINTS\Altium_Footprint_Lib.PcbLib; Height: 0.35MM; Library Path: Y:\MIS_DATABASE\Library\ALTIUM_TOOL\SCHEMATICS_PARTS\MS_OPTO_Library.schlib; Mfr_name: WURTH ELECTRONICS; Mistral Part No: 130020090020-R; Package: SMD; Part_type: OPTO\LED; Project: AM64X_SKEVM; RoHS: RoHS; Temperature: -40°C+85°C; Tolerance: NA; Voltage: NA; Wattage: NA; Weight: 29.3mg; Datasheet: Y:\MIS_DATABASE\DATASHEETS\DISCRETES\LEDS\150040RS73220.PDF
LD5 LD6 = DIODE_LED: DIODE LED AMBER SMD; Chkd/date: MANIRAJA/100920; Crtd /date: ALVY/100920; Custom_Duty: 24%; Customs_HS_Code: 85439000; Distributor_name: DIGIKEY; Distributor_part_number: 732-13423-1-ND; Footprint Path: Y:\MIS_DATABASE\Library\ALTIUM_TOOL\PCB_FOOTPRINTS\Altium_Footprint_Lib.PcbLib; Height: 0.35MM; Library Path: Y:\MIS_DATABASE\Library\ALTIUM_TOOL\SCHEMATICS_PARTS\MS_OPTO_Library.schlib; Mfr_name: WURTH ELECTRONICS; Mistral Part No: 130020090022-R; Package: SMD; Part_type: OPTO\LED; Project: AM64X_SKEVM; RoHS: RoHS; Temperature: -40°C+85°C; Tolerance: NA; Voltage: NA; Wattage: NA; Weight: 29.3mg; Datasheet: Y:\MIS_DATABASE\DATASHEETS\DISCRETES\LEDS\150040AS73220.PDF
R65 R360 R732-R736 R738-R742 = RESISTOR: RES 22E 1/20W 5% 0201; Chkd/date: PRADEEP/220424; Crtd /date: SHANKARI/220424; Custom_Duty: 15%; Customs_HS_Code: 85332119; Distributor_name: DIGIKEY; Distributor_part_number: 311-22NCT-ND; Footprint Path: Y:\MIS_DATABASE\Library\ALTIUM_TOOL\PCB_FOOTPRINTS\Altium_Footprint_Lib.PcbLib; Height: 0.26MM; Library Path: Y:\MIS_DATABASE\Library\ALTIUM_TOOL\SCHEMATICS_PARTS\MS_DISCRETE_Library.schlib; Manufacturer: YAGEO; Mfr_name: YAGEO; Mfr_part_number: RC0201JR-0722RL; Mistral Part No: 110024040012-R; Package: 0201; Part_type: RESISTORS\FIXED; Project: J7AEN_SKEVM; RoHS: RoHS; Temperature: -55°C+125°C; Tolerance: 5%; Voltage: NA; Wattage: 1/20W; Weight: NA; Datasheet: Y:\MIS_DATABASE\DATASHEETS\RESISTORS\RC0201JR-0722RL.PDF
R159 R161 R166-R168 R170 R171 R175 = RESISTOR: RES 220E 1/10W 5% 0402; Chkd/date: VASANTHA/291216; Crtd /date: GEETHA/260406; Custom_Duty: 15%; Customs_HS_Code: 85332119; Distributor_name: DIGIKEY; Distributor_part_number: P220JCT-ND; Footprint Path: Y:\MIS_DATABASE\Library\ALTIUM_TOOL\PCB_FOOTPRINTS\Altium_Footprint_Lib.PcbLib; Height: 0.40MM; Library Path: Y:\MIS_DATABASE\Library\ALTIUM_TOOL\SCHEMATICS_PARTS\MS_DISCRETE_Library.schlib; Manufacturer: PANASONIC-ECG; Mfr_name: PANASONIC-ECG; Mfr_part_number: ERJ-2GEJ221X; Mistral Part No: 110009030506-R; Package: 0402; Part_type: RESISTORS\FIXED; Project: RED EYE; RoHS: RoHS; Temperature: -55°C+155°C; Tolerance: 5%; Voltage: NA; Wattage: 1/10W; Weight: 0.8mg; Datasheet: Y:\MIS_DATABASE\DATASHEETS\RESISTORS\PAN-ERJSER_NOV17.PDF
R369 R372 R382 = RESISTOR: RES 22E 1/16W 5% 0402; Chkd/date: ALVY/210122; Crtd /date: TAMILARASU/210122; Custom_Duty: 15%; Customs_HS_Code: 85332119; Distributor_name: DIGIKEY; Distributor_part_number: 311-22JRCT-ND; Footprint Path: Y:\MIS_DATABASE\Library\ALTIUM_TOOL\PCB_FOOTPRINTS\Altium_Footprint_Lib.PcbLib; Height: 0.40MM; Library Path: Y:\MIS_DATABASE\Library\ALTIUM_TOOL\SCHEMATICS_PARTS\MS_DISCRETE_Library.schlib; Manufacturer: YAGEO; Mfr_name: YAGEO AMERICA; Mfr_part_number: RC0402JR-0722RL; Mistral Part No: 110022010018-R; Package: 0402; Part_type: RESISTORS\FIXED; Project: DLRL DIGITAL RECEIVER_BRD; RoHS: RoHS; Temperature: -55°C+155°C; Tolerance: 5%; Voltage: NA; Wattage: 1/16W; Weight: 0.65mg; Datasheet: Y:\MIS_DATABASE\DATASHEETS\RESISTORS\RCXXXXP-SER_SEP18.PDF
U38 = TPIC2810D_SOIC16: IC 8-BIT LED DRIVER WITH I2C INTERFACE SOIC16; Chkd/date: MANIRAJA/230817; Crtd /date: MANIRAJA/220817; Custom_Duty: 15%; Customs_HS_Code: 85423100; Distributor_name: DIGIKEY; Distributor_part_number: 296-13746-5-ND; Height: 1.75MM; Mfr_name: TEXAS INSTRUMENTS; Mistral Part No: 141017080026-R; Package: SOIC16; Part_type: ICS\INTERFACE; Project: TI_MAXIE_CPB; RoHS: RoHS; Temperature: -40°C+125°C; Tolerance: NA; Voltage: NA; Wattage: NA; Weight: NA; Datasheet: Y:\MIS_DATABASE\DATASHEETS\ICS\INTERFACE\TPIC2810D.PDF
U52 = LMK1C1103_TSSOP8: IC 3-CHANNEL LVCMOS CLOCK BUFFER TSSOP8; Chkd/date: MANIRAJA/080920; Crtd /date: ALVY/070920; Custom_Duty: 15%; Customs_HS_Code: 85423100; Distributor_name: DIGIKEY; Distributor_part_number: 296-LMK1C1103PWRCT-ND; Footprint Path: Y:\MIS_DATABASE\Library\ALTIUM_TOOL\PCB_FOOTPRINTS\Altium_Footprint_Lib.PcbLib; Height: 1.20MM; Library Path: Y:\MIS_DATABASE\Library\ALTIUM_TOOL\SCHEMATICS_PARTS\MS_COMBINATIONAL_Library.schlib; Mfr_name: TEXAS INSTRUMENTS; Mistral Part No: 141020090002-R; Package: TSSOP8; Part_type: ICS\DIGITAL\COMBINATIONAL; Project: AM64X_SKEVM; RoHS: RoHS; Temperature: -40°C+125°C; Tolerance: NA; Voltage: NA; Wattage: NA; Weight: 34.1mg; Datasheet: Y:\MIS_DATABASE\DATASHEETS\ICS\DIGITAL\COMBINATIONAL\LMK1C110X.PDF
J23 = CON_FLEX_40X1_FH12A-40S-0.5SH: CON FPC 40X1 0.50MM PITCH RT TOP SMD; Chkd/date: SHREESHAIL/201106; Crtd /date: MAZHAR/171106; Custom_Duty: 24%; Customs_HS_Code: 85369090; Distributor_name: DIGIKEY; Distributor_part_number: HFK40CT-ND; Height: 2.00MM; Mfr_name: HIROSE ELECTRIC EUROPE; Mfr_part_number: FH12A-40S-0.5SH(55); Mistral Part No: 150009030176-R; Package: SMD; Part_type: CONNECTOR\FPC; Project: PMP LCD BOARD; Datasheet: Y:\MIS_DATABASE\DATASHEETS\CONNECTORS\FH12SERIES.PDF
R498 R499 R581 R600 = RESISTOR: RES 4.7K 1/20W 5% 0201; Chkd/date: MANIRAJA/200921; Crtd /date: ALVY/200921; Custom_Duty: 15%; Customs_HS_Code: 85332119; Distributor_name: DIGIKEY; Distributor_part_number: 311-4.7KNCT-ND; Footprint Path: Y:\MIS_DATABASE\Library\ALTIUM_TOOL\PCB_FOOTPRINTS\Altium_Footprint_Lib.PcbLib; Height: 0.26MM; Library Path: Y:\MIS_DATABASE\Library\ALTIUM_TOOL\SCHEMATICS_PARTS\MS_DISCRETE_Library.schlib; Mfr_name: YAGEO AMERICA; Mfr_part_number: RC0201JR-074K7L; Mistral Part No: 110021090007-R; Package: 0201; Part_type: RESISTORS\FIXED; Project: TI_AM62x SKEVM_BRD; RoHS: RoHS; Temperature: -55°C+125°C; Tolerance: 5%; Voltage: NA; Wattage: 1/20W; Weight: 0.17mg; Datasheet: Y:\MIS_DATABASE\DATASHEETS\RESISTORS\RCXXXXL-SER_MAR18.PDF
R582 = RESISTOR: RES 0E 1/8W 5% 0805; Chkd/date: VASANTHA/130416; Crtd /date: JEBRAN/020316; Custom_Duty: 15%; Customs_HS_Code: 85332119; Distributor_name: DIGIKEY; Distributor_part_number: 311-0.0ARCT-ND; Footprint Path: Y:\MIS_DATABASE\Library\ALTIUM_TOOL\PCB_FOOTPRINTS\Altium_Footprint_Lib.PcbLib; Height: 0.60MM; Library Path: Y:\MIS_DATABASE\Library\ALTIUM_TOOL\SCHEMATICS_PARTS\MS_DISCRETE_Library.schlib; Mfr_name: YAGEO AMERICA; Mfr_part_number: RC0805JR-070RL; Mistral Part No: 110009030074-R; Package: 0805; Part_type: RESISTORS\FIXED; Project: ZK_BIOMETRIC; RoHS: RoHS; Temperature: -55°C+155°C; Tolerance: 5%; Voltage: NA; Wattage: 1/8W; Weight: 5.5mg; Datasheet: Y:\MIS_DATABASE\DATASHEETS\RESISTORS\RCXXXXL-SER_MAR18.PDF
U42 = TCA9517DGKR_VSSOP8: IC 2-CHANNEL BI-DIR LEVEL-SHIFTING I2C BUS REPEATER SOIC8; Chkd/date: MANIRAJA/171121; Crtd /date: ALVY/161121; Custom_Duty: 15%; Customs_HS_Code: 85423100; Distributor_name: DIGIKEY; Distributor_part_number: 296-39221-1-ND; Footprint Path: Y:\MIS_DATABASE\Library\ALTIUM_TOOL\PCB_FOOTPRINTS\Altium_Footprint_Lib.PcbLib; Height: 1.75MM; Library Path: Y:\MIS_DATABASE\Library\ALTIUM_TOOL\SCHEMATICS_PARTS\MS_MISCINTERFACE_Library.schlib; Mfr_name: TEXAS INSTRUMENTS; Mistral Part No: 141021110017-R; Package: SOIC8; Part_type: ICS\INTERFACE\LEVEL TRANSLATOR; Project: EXCITER MULTI-CH RX UNIT; RoHS: RoHS; Temperature: -40°C+85°C; Tolerance: NA; Voltage: NA; Wattage: NA; Weight: 540mg; Datasheet: Y:\MIS_DATABASE\DATASHEETS\ICS\INTERFACE\TCA9517.PDF
U12 = AM62-EVM_BGA425: IC AM62 SoC MICROPROCESSOR BGA425; Chkd/date: ALVY/110621; Crtd /date: MANIRAJA/110621; Custom_Duty: 15%; Customs_HS_Code: 85423100; Distributor_name: NA; Distributor_part_number: NA; Footprint Path: Y:\MIS_DATABASE\Library\ALTIUM_TOOL\PCB_FOOTPRINTS\Altium_Footprint_Lib.PcbLib; Height: 0.65MM; Library Path: Y:\MIS_DATABASE\Library\ALTIUM_TOOL\SCHEMATICS_PARTS\MS_MICROPROCESSOR_Library.schlib; Mfr_name: TEXAS INSTRUMENTS; Mistral Part No: 141221060001; Package: BGA425; Part_type: ICS\DIGITAL\MICROPROCESSOR; Project: AM62_EVM_BRD; RoHS: NA; Temperature: NA; Tolerance: NA; Voltage: NA; Wattage: NA; Weight: NA; Datasheet: Y:\MIS_DATABASE\DATASHEETS\ICS\DIGITAL\MICROCONTROLLER\AM62-SoC_SVB.PDF

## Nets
DGND: C19.2 C21.2 C22.2 C24.2 C25.2 C26.2 C27.2 C28.2 C29.2 C32.2 C33.1 C35.2 C38.2 C39.2 C157.2 C159.2 C166.2 C195.2 C208.2 C216.2 C224.2 C227.2 C228.2 C234.1 C235.2 C236.2 C237.2 C238.2 C242.2 C324.1 C325.1 C326.1 C375.2 C474.2 C477.2 J4.1(CH-GND) J23.7 J23.16 J23.25 J23.34 J23.40 J23.41 J23.42 Q4.4(S1) Q4.7(S2) Q5.4(S1) Q5.7(S2) Q6.4(S1) Q6.7(S2) R29.2 R35.2 R47.1 R49.1 R54.1 R160.2 R162.2 R169.2 R195.2 R292.1 R293.1 R295.1 R299.1 R328.2 R712.1 U38.8(~{G}) U38.16(GND) U41.2(GND) U42.4(GND) U49.49(GND) U52.4(GND) ; also on sheet 1 3 12 13 14 15 16 17 18 19 20 21 22 23 24 25 29 30 31 32 33 34 35 36 37 38 39 40 41 42 43 44 45
VCC1V8_CLKBUF: C324.2 C325.2 C326.2 FL22.2 R380.2 U52.6(VDD) ; also on sheet 44
VCC3V3_TA: C166.1 C474.1 C477.1 J23.1 J23.2 J23.3 R218.1 R498.1 R499.1 R566.2 R567.2 R568.2 R581.1 R582.1 R585.2 R586.2 R587.2 R600.1 U42.8(VCCB) ; also on sheet 3 29
VCC_1V8: FL22.1 ; also on sheet 14 15 20 21 23 36 39 41 42 44
VCC_3V3_MAIN: R582.2 ; also on sheet 1 14 15
VCC_3V3_SYS: C19.1 C32.1 C38.1 C157.1 C159.1 C208.1 C227.1 C235.1 C236.1 C242.1 C375.1 FL15.1 R38.2 R159.1 R161.1 R166.1 R167.1 R168.1 R170.1 R171.1 R175.1 R196.2 R197.2 R286.1 R288.2 R291.2 R294.2 R298.1 R300.2 R311.2 R322.2 R329.1 R330.2 R334.2 R672.1 U38.1(VCC) U41.5(VCC) U42.1(VCCA) U49.19(VDDIO) U49.30(VDDIO) U49.41(VDDIO) ; also on sheet 3 12 14 15 16 20 21 22 24 25 29 31 32 33 34 35 36 37 38 39 40 41 42 43 44 45
VDD_1V0: C21.1 C22.1 C26.1 C27.1 C28.1 C29.1 C39.1 C224.1 C237.1 C238.1 U49.6(VDD1P0) U49.24(VDD1P0) U49.31(VDD1P0) U49.42(VDD1P0) ; also on sheet 14 25
VDD_2V5: C24.1 C25.1 C33.2 C35.1 C216.1 C228.1 U49.3(VDDA2P5) U49.9(VDDA2P5) ; also on sheet 15 19 25
BOOTMODE_I2C_SCL: R589.1 R600.2 ; also on sheet 3 29
BOOTMODE_I2C_SDA: R581.2 R591.1 ; also on sheet 3 29
CLKOUT0: U52.1(CLKIN) ; also on sheet 44
CPSW2_GPIO_0: J4.14 Q6.1(D1) Q6.2(D2) Q6.5(D3) Q6.6(D4) Q6.8(D5) R334.1
CPSW2_LED_1000: J4.12 Q4.1(D1) Q4.2(D2) Q4.5(D3) Q4.6(D4) Q4.8(D5)
CPSW2_LED_ACT: J4.13 Q5.1(D1) Q5.2(D2) Q5.5(D3) Q5.6(D4) Q5.8(D5) R288.1
CPSW_ETH2_D0N: J4.10(MX0-) U49.2(TD_M_A)
CPSW_ETH2_D0P: J4.9(MX0+) U49.1(TD_P_A)
CPSW_ETH2_D1M: J4.8(MX1-) U49.5(TD_M_B)
CPSW_ETH2_D1P: J4.7(MX1+) U49.4(TD_P_B)
CPSW_ETH2_D2M: J4.6(MX2-) U49.8(TD_M_C)
CPSW_ETH2_D2P: J4.5(MX2+) U49.7(TD_P_C)
CPSW_ETH2_D3M: J4.4(MX3-) U49.11(TD_M_D)
CPSW_ETH2_D3P: J4.3(MX3+) U49.10(TD_P_D)
CPSW_ETH2_GPIO_0: R293.2 R294.1 R302.1 R340.1 TP12.1(TP)
CPSW_ETH2_GPIO_1: R291.1 R292.2 R301.1 TP13.1(TP)
CPSW_ETH2_LED0: TP15.1(TP) U49.47(LED_0)
CPSW_ETH2_LED_1000: R47.2 R289.1 R300.1 TP17.1(TP) U49.46(LED_1)
CPSW_ETH2_LED_ACT: R38.1 R295.2 R338.1 TP11.1(TP) U49.45(LED_2)
CPSW_RGMII1_ETH1_CLK: R382.2 ; also on sheet 25
CPSW_RGMII1_RD0: U12.AB17(RGMII1_RD0) ; also on sheet 25
CPSW_RGMII1_RD1: U12.AC17(RGMII1_RD1) ; also on sheet 25
CPSW_RGMII1_RD2: U12.AB16(RGMII1_RD2) ; also on sheet 25
CPSW_RGMII1_RD3: U12.AA15(RGMII1_RD3) ; also on sheet 25
CPSW_RGMII1_RX_CTL: U12.AE17(RGMII1_RX_CTL) ; also on sheet 25
CPSW_RGMII1_RXC: U12.AD17(RGMII1_RXC) ; also on sheet 25
CPSW_RGMII1_TD0: R732.2 ; also on sheet 25
CPSW_RGMII1_TD0_R: R732.1 U12.AE20(RGMII1_TD0)
CPSW_RGMII1_TD1: R733.2 ; also on sheet 25
CPSW_RGMII1_TD1_R: R733.1 U12.AD20(RGMII1_TD1)
CPSW_RGMII1_TD2: R734.2 ; also on sheet 25
CPSW_RGMII1_TD2_R: R734.1 U12.AE18(RGMII1_TD2)
CPSW_RGMII1_TD3: R735.2 ; also on sheet 25
CPSW_RGMII1_TD3_R: R735.1 U12.AD18(RGMII1_TD3)
CPSW_RGMII1_TX_CTL: R736.2 ; also on sheet 25
CPSW_RGMII1_TX_CTL_R: R736.1 U12.AD19(RGMII1_TX_CTL)
CPSW_RGMII1_TXC: R360.2 ; also on sheet 25
CPSW_RGMII1_TXC_R: R360.1 U12.AE19(RGMII1_TXC)
CPSW_RGMII2_ETH2_CLK: R369.2 U49.15(XI)
CPSW_RGMII2_ETH2_CLK_OUT: TP20.1(TP) U49.18(CLK_OUT)
CPSW_RGMII2_ETH2_RBIAS: C234.2 R328.1 U49.12(RBIAS)
CPSW_RGMII2_MDC: R329.2 R673.2 U49.16(MDC)
CPSW_RGMII2_MDIO: R330.1 R674.2 U49.17(MDIO)
CPSW_RGMII2_RD0: R54.2 R322.1 U12.AE23(RGMII2_RD0) U49.33(RX_D0)
CPSW_RGMII2_RD1: U12.AB20(RGMII2_RD1) U49.34(RX_D1)
CPSW_RGMII2_RD2: R49.2 R311.1 U12.AC21(RGMII2_RD2) U49.35(RX_D2)
CPSW_RGMII2_RD3: U12.AE22(RGMII2_RD3) U49.36(RX_D3)
CPSW_RGMII2_RESETn: R35.1 U41.4(Y) U49.43(RESET_N)
CPSW_RGMII2_RX_CTL: R298.2 R299.2 U12.AD22(RGMII2_RX_CTL) U49.38(RX_DV/RX_CTRL)
CPSW_RGMII2_RXC: R324.1 U12.AD23(RGMII2_RXC)
CPSW_RGMII2_TD0: R738.2 U49.28(TX_D0)
CPSW_RGMII2_TD0_R: R738.1 U12.Y18(RGMII2_TD0)
CPSW_RGMII2_TD1: R739.2 U49.27(TX_D1)
CPSW_RGMII2_TD1_R: R739.1 U12.AA18(RGMII2_TD1)
CPSW_RGMII2_TD2: R740.2 U49.26(TX_D2)
CPSW_RGMII2_TD2_R: R740.1 U12.AD21(RGMII2_TD2)
CPSW_RGMII2_TD3: R741.2 U49.25(TX_D3)
CPSW_RGMII2_TD3_R: R741.1 U12.AC20(RGMII2_TD3)
CPSW_RGMII2_TX_CTL: R742.2 U49.37(TX_EN/TX_CTRL)
CPSW_RGMII2_TX_CTL_R: R742.1 U12.AA19(RGMII2_TX_CTL)
CPSW_RGMII2_TXC: R65.2 U49.29(GTX_CLK)
CPSW_RGMII2_TXC_R: R65.1 U12.AE21(RGMII2_TXC)
CPSW_RGMII_INTn: R672.2 U49.44(INT/PWDN) ; also on sheet 25
ETH2_EARTH: C195.1 J4.15(SH1) J4.16(SH2) R29.1
GPIO_CPSW2_RST: R731.2 ; also on sheet 41
LED1: LD9.1(CATHODE) U38.3(DRAIN0)
LED2: LD8.1(CATHODE) U38.4(DRAIN1)
LED3: LD7.1(CATHODE) U38.5(DRAIN2)
LED4: LD6.1(CATHODE) U38.6(DRAIN3)
LED5: LD2.1(CATHODE) U38.11(DRAIN4)
LED6: LD3.1(CATHODE) U38.12(DRAIN5)
LED7: LD4.1(CATHODE) U38.13(DRAIN6)
LED8: LD5.1(CATHODE) U38.14(DRAIN7)
PORz_OUT: U41.3(B) ; also on sheet 22 25 29 44
RESETSTATz: R194.1 ; also on sheet 15 21 22 23 25 29 34 35 39 41 42 43 44
SoC_CLKIN: R372.2 ; also on sheet 36
SOC_I2C1_SCL: U42.2(SCLA) ; also on sheet 3 16 24 41 42 43 44
SOC_I2C1_SDA: U42.3(SDAA) ; also on sheet 3 16 24 41 42 43 44
SoC_I2C1_TA_SCL: R499.2 R583.1 U42.7(SCLB)
SoC_I2C1_TA_SDA: R498.2 R590.1 U42.6(SDAB)
SOC_RGMII_MDC: R673.1 ; also on sheet 25 34
SOC_RGMII_MDIO: R674.1 ; also on sheet 25 34
TEST_GPIO1: R587.1 R596.1 ; also on sheet 3 45
TEST_GPIO2: R567.1 R571.1 TP117.1(TP) ; also on sheet 3
TEST_GPIO3: R597.1 TP73.1(TP) ; also on sheet 3 29
TEST_GPIO4: R568.1 R569.1 TP74.1(TP) ; also on sheet 3 29
TEST_PORZn: R586.1 R595.1 ; also on sheet 3 44
TEST_POWERDOWN: R585.1 R594.1 ; also on sheet 3 15
TEST_WARMRESETn: R566.1 R570.1 ; also on sheet 3 45
WKUP_I2C0_SCL: U38.15(SCL) ; also on sheet 34
WKUP_I2C0_SDA: U38.2(SDA) ; also on sheet 34
N16800246: FL15.2 J4.2(VCC)
N16943223: R380.1 U52.2(1G)
N16943354: R372.1 U52.3(Y0)
N16943356: R382.1 U52.8(Y1)
N16943358: R369.1 U52.5(Y2)
N16944941: LD9.2(ANODE) R175.2
N16944943: LD8.2(ANODE) R171.2
N16944955: LD7.2(ANODE) R170.2
N16944965: LD6.2(ANODE) R168.2
N16944969: LD2.2(ANODE) R159.2
N16944978: LD3.2(ANODE) R161.2
N16944987: LD4.2(ANODE) R166.2
N16944997: LD5.2(ANODE) R167.2
N16945140: R169.1 U38.7(A2)
N16945144: R162.1 U38.10(A1)
N16945148: R160.1 U38.9(A0)
N16990175: J23.27 R595.2
N16990176: J23.30 R596.2
N16990179: J23.31 R571.2
N16990180: J23.32 R597.2
N16990246: J23.26 R594.2
N16990247: J23.28 R570.2
N16990252: J23.33 R569.2
N17149186: TP101.1(TP) U49.13(VDDA1P8)
N17149287: J4.11 R286.2
N17167691: R324.2 U49.32(RX_CLK)
N17434691: TP19.1(TP) U49.48(VDDA1P8)
N17473283: R194.2 R197.1 U41.6(C)
N17473293: R195.1 R196.1 R731.1 U41.1(A)
N17654451: Q4.3(G) R289.2
N17799775: Q6.3(G) R340.2
N17800599: Q5.3(G) R338.2
N18374804: J23.36 R583.2
N18374807: J23.37 R589.2
N18374810: J23.38 R590.2
N18374813: J23.39 R591.2
N18576730: R302.2 U49.39(GPIO_0)
N18576733: R301.2 U49.40(GPIO_1)
N20274420: TP103.1(TP) U49.14(XO)
N22265373: R218.2 R712.2 U42.5(EN)

Not connected (* = marked no-connect by the designer): J23 4* 5* 6* 8* 9* 10* 11* 12* 13* 14* 15* 17* 18* 19* 20* 21* 22* 23* 24* 29* 35*; U49 20(JTAG_CLK)* 21(JTAG_TDO)* 22(JTAG_TMS)* 23(JTAG_TDI)*; U52 7(NC)*

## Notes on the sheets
sheet 26
- D-Note:
  Ok to use 0402 package for 1uF cap to
  match the 10uF bulk cap package size
- CPSW3G RGMII 2 - ETHERNET PHY
- D-Note:
  The caps and values used are  as per the
  EPHY data sheet recommendations.
- D-Note:
  Refer to DP83867ERGZ-R-EVM when using Discrete LAN
  Transformer Module and RJ45 connector.
- R-Note:
  Ferrite is DNI.
- D-Note:
  Refer Custom Board Design and Simulation Guidelines for
  Processor High Speed Parallel Interfaces
  https://www.ti.com/lit/pdf/sdaa087
- D-Note:
  Verify the power sequence requirements
  for Two-Supply Configuration and
  Three-Supply Configuration.
- RJ45 CONNECTOR WITH
  INTEGRATED MAGNETICS
- 100E
- 100E
- D-Note:
  Provide provision for series resistor
  based on EPHY for RDX signals near
  to the EPHY.
- 100E
- 100E
- D-Note:
  Refer to the EPHY EVM for JTAG connections.
- V
- D-Note:
  RBIAS resistor value has
  been reduced from 11K
  and a parallel capacitor
  has been added to improve
  Ethernet compliance
  testing performance
- D-Note:
  ANDing logic could be optimized to a 2-input AND gate. Use RESETSTATz (or
  PORz_OUT) and the SoC IO as inputs to the ANDing logic.
- Silk: CPSW PHY-2
- Note:
  Pull-up is enabled for GPIO input.
  RESETSTATz series resistor is DNI.
- D-Note:
  ANDing logic additionally performs level translation. Verify
  the reset IO level compatibility before optimizing the reset
  ANDing logic. IO level mismatch can cause residual voltage
  (supply leakage) and affect PMIC/SoC operation.
- PHY ADDRESS = 00001
- Auto-negotiation Enabled
- 10/100/1000 advertised, Auto-MDI-X
- Tx Clock Skew = 0ns
- Rx Clock Skew = 2ns
sheet 27
- SOC MAC INTERFACE
- D-Note:
  Series Resistor provision is provided for the TDx MAC
  interface signals near to the processor pins for control of
  possible signal reflections
- CLOCK BUFFER FOR SOC AND ETHERNET PHYs
- C
- D-Note:
  DNI SOC_CLKIN series resistor when
  crystal option is used for SOC clocking
  and SOC clock output is used for clocking
  the peripherals
- C
- LED DRIVER
- GREEN
- RED
- GREEN
- AMBER
- GREEN
- RED
- GREEN
- AMBER
- I2C ADDRESS: 0x60
sheet 28
- 40-PIN TEST AUTOMATION HEADER
- I2C BUS BUFFER
- Silk: AUTOMATION HDR
- TEST AUTOMATION GPIO MAPPING
- Internal/
  External
  PU/PD states
- SIGNAL NAME
- DESCRIPTION
- Direction WRT CTRL
- OUTPUT
  OUTPUT
  OUTPUT
  OUTPUT
  OUTPUT
  OUTPUT
  OUTPUT
- TEST_POWERDOWN
  TEST_PORZn
  TEST_WARMRESETn
  TEST_GPIO1
  TEST_GPIO2
  TEST_GPIO3
  TEST_GPIO4
- Used to Power down the EVM
  Used to  Reset the SoC PORz
  Used to Reset the SoC Warmreset
  Used to Generate the interrupt on
  MCU_GPIO0_15 Pin
  Connected to a Testpoint
  Used to Enable the BOOTMODE Buffer
  Used to Reset the Bootmode I2C IO Expander
- External Pullup
  External Pullup
  External Pullup
  External Pullup
  External Pullup
  External Pullup
  External Pullup
